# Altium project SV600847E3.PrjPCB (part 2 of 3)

## Sheet SV600847E3_4_LMK04828.SchDoc
size 431 x 279 mm; Date: Not shown in title block; ApprovedBy: Not shown in title block; CheckedBy: Not shown in title block; Author: Not shown in title block; CompanyName: Not shown in title block; Engineer: Not shown in title block; Organization: Not shown in title block; Address1: Not shown in title block; Address2: Not shown in title block; Address3: Not shown in title block; Address4: Not shown in title block; DocumentNumber: 4; Revision: Use project parameter SCH_Rev; SheetNumber: 4; SheetTotal: 7; PageSetup: Record=PageOptions|CenterHorizontal=True|CenterVertical=True|PrintScale=0.47|XCorrection=1.00|YCorrection=1.00|PrintKind=0|BorderSize=5000000|LeftOffset=0|BottomOffset=0|Orientation=2|PaperLength=1000|PaperWidth=1000|Scale=100|PaperSource=7|PrintQuality=600|MediaType=1|DitherType=10|PaperKind=11" x 17"|PrintScaleMode=1
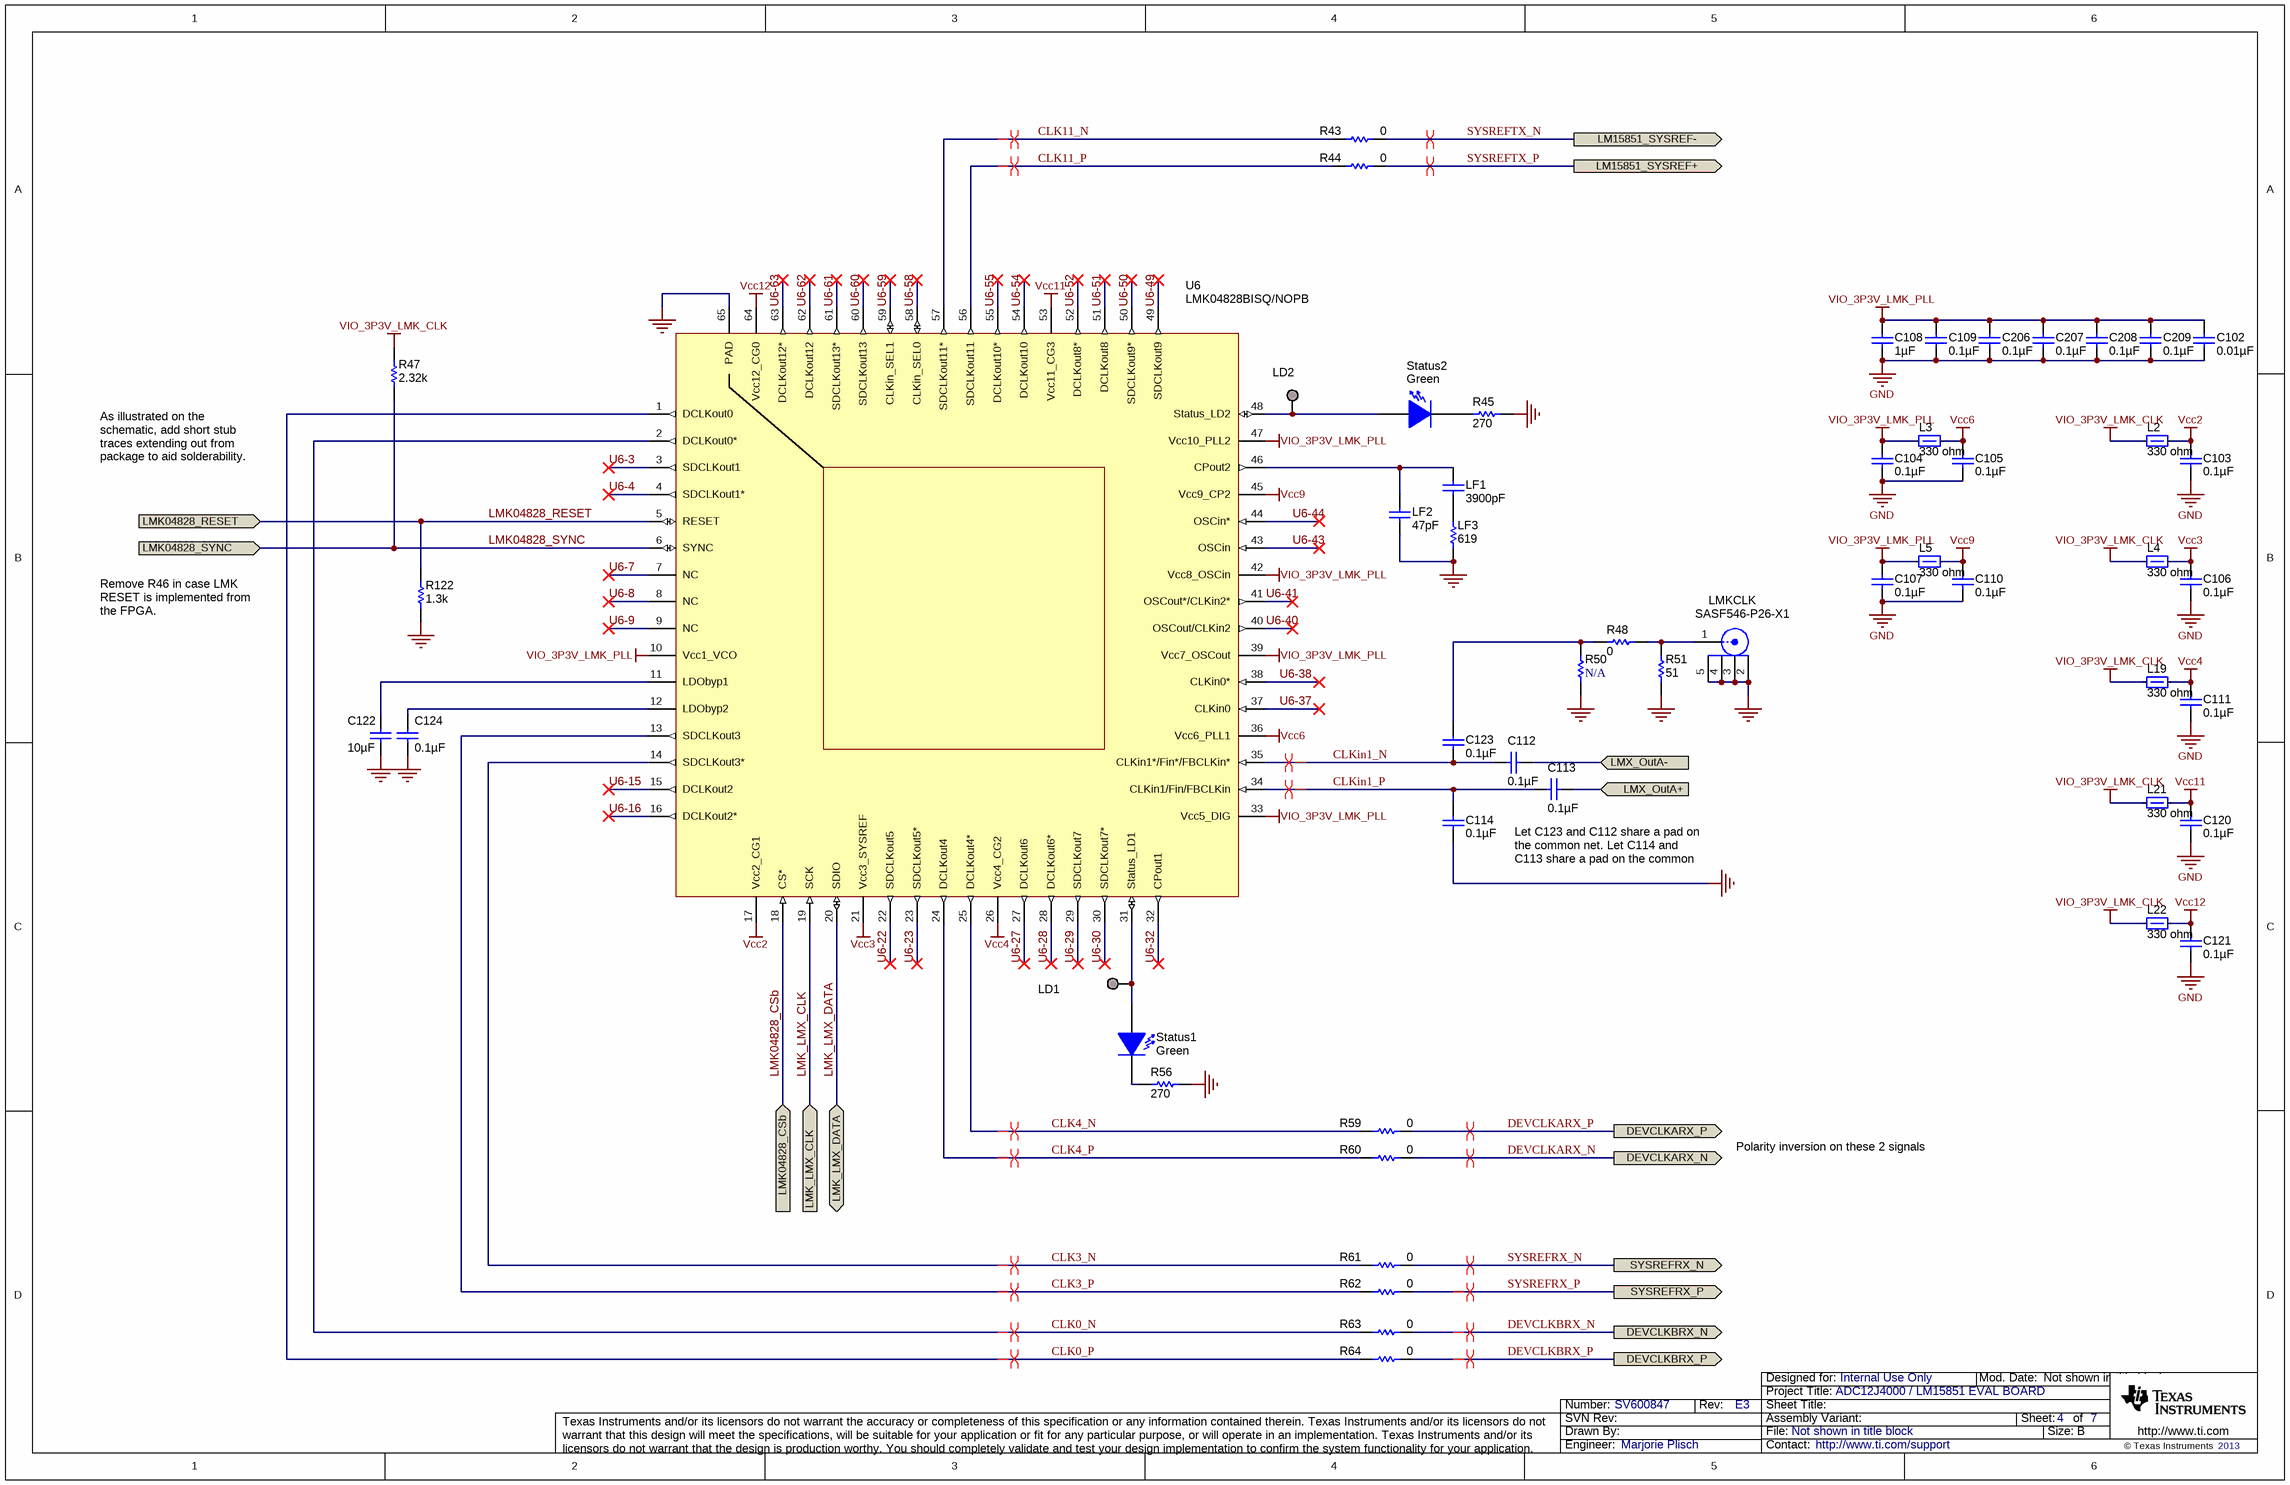
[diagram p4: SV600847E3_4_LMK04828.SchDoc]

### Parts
C102  ValueDisplayed: 0.01µF  [0402L]  (hidden comment: C1005X7R1C103K)
C103  ValueDisplayed: 0.1µF  [0402L]  (hidden comment: C1005X5R1A104K)
C104  ValueDisplayed: 0.1µF  [0402L]  (hidden comment: C1005X5R1A104K)
C105  ValueDisplayed: 0.1µF  [0402L]  (hidden comment: C1005X5R1A104K)
C106  ValueDisplayed: 0.1µF  [0402L]  (hidden comment: C1005X5R1A104K)
C107  ValueDisplayed: 0.1µF  [0402L]  (hidden comment: C1005X5R1A104K)
C108  ValueDisplayed: 1µF  [0603L]  (hidden comment: C1608X5R1C105K)
C109  ValueDisplayed: 0.1µF  [0402L]  (hidden comment: C1005X5R1A104K)
C110  ValueDisplayed: 0.1µF  [0402L]  (hidden comment: C1005X5R1A104K)
C111  ValueDisplayed: 0.1µF  [0402L]  (hidden comment: C1005X5R1A104K)
C112  ValueDisplayed: 0.1µF  [0402L]  (hidden comment: C1005X5R1A104K)
C113  ValueDisplayed: 0.1µF  [0402L]  (hidden comment: C1005X5R1A104K)
C114  ValueDisplayed: 0.1µF  [0402L]  (hidden comment: C1005X5R1A104K)
C120  ValueDisplayed: 0.1µF  [0402L]  (hidden comment: C1005X5R1A104K)
C121  ValueDisplayed: 0.1µF  [0402L]  (hidden comment: C1005X5R1A104K)
C122  ValueDisplayed: 10µF  [0805L]  (hidden comment: C0805C106K8PACTU)
C123  ValueDisplayed: 0.1µF  [0402L]  (hidden comment: C1005X5R1A104K)
C124  ValueDisplayed: 0.1µF  [0402L]  (hidden comment: C1005X5R1A104K)
C206  ValueDisplayed: 0.1µF  [0402L]  (hidden comment: C1005X5R1A104K)
C207  ValueDisplayed: 0.1µF  [0402L]  (hidden comment: C1005X5R1A104K)
C208  ValueDisplayed: 0.1µF  [0402L]  (hidden comment: C1005X5R1A104K)
C209  ValueDisplayed: 0.1µF  [0402L]  (hidden comment: C1005X5R1A104K)
L2  value 330 ohm  [0603]  (hidden comment: BLM18SG331TN1D)
L3  value 330 ohm  [0603]  (hidden comment: BLM18SG331TN1D)
L4  value 330 ohm  [0603]  (hidden comment: BLM18SG331TN1D)
L5  value 330 ohm  [0603]  (hidden comment: BLM18SG331TN1D)
L19  value 330 ohm  [0603]  (hidden comment: BLM18SG331TN1D)
L21  value 330 ohm  [0603]  (hidden comment: BLM18SG331TN1D)
L22  value 330 ohm  [0603]  (hidden comment: BLM18SG331TN1D)
LD1  TESTPOINT  [TESTPOINT]  (value not drawn)  (no BOM)
LD2  TESTPOINT  [TESTPOINT]  (value not drawn)  (no BOM)
LF1  ValueDisplayed: 3900pF  [0603L]  (hidden comment: C1608C0G1E392J)
LF2  ValueDisplayed: 47pF  [0603L]  (hidden comment: 06035A470JAT2A)
LF3  value 619  [0603L]  (hidden comment: RC0603FR-07619RL)
LMKCLK  SASF546-P26-X1  [CONN_LTI_SASF546-P26-X1]
R43  value 0  [0402L]  (hidden comment: CRCW04020000Z0ED)
R44  value 0  [0402L]  (hidden comment: CRCW04020000Z0ED)
R45  value 270  [0603L]  (hidden comment: CRCW0603270RJNEA)
R47  value 2.32k  [0603L]  (hidden comment: RC0603FR-072K32L)
R48  value 0  [0402L]  (hidden comment: CRCW04020000Z0ED)
R50  (no value)  [0402L]
R51  value 51  [0402L]  (hidden comment: CRCW040251R0JNED)
R56  value 270  [0603L]  (hidden comment: CRCW0603270RJNEA)
R59  value 0  [0402L]  (hidden comment: CRCW04020000Z0ED)
R60  value 0  [0402L]  (hidden comment: CRCW04020000Z0ED)
R61  value 0  [0402L]  (hidden comment: CRCW04020000Z0ED)
R62  value 0  [0402L]  (hidden comment: CRCW04020000Z0ED)
R63  value 0  [0402L]  (hidden comment: CRCW04020000Z0ED)
R64  value 0  [0402L]  (hidden comment: CRCW04020000Z0ED)
R122  value 1.3k  [0603L]  (hidden comment: RC0603JR-071K3L)
Status1  value Green  [LED_LTST-C190]  (hidden comment: LTST-C190GKT)
Status2  value Green  [LED_LTST-C190]  (hidden comment: LTST-C190GKT)
U6  LMK04828BISQ/NOPB  [NKD0064A]

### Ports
DEVCLKARX_N (out), DEVCLKARX_P (out), DEVCLKBRX_N (out), DEVCLKBRX_P (out), LM15851_SYSREF+ (out), LM15851_SYSREF- (out), LMK04828_CSb (in), LMK04828_RESET (in), LMK04828_SYNC (in), LMK_LMX_CLK (in), LMK_LMX_DATA (bidir), LMX_OutA+ (in), LMX_OutA- (in), SYSREFRX_N (out), SYSREFRX_P (out)

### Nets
GND: C102.2 C103.2 C104.2 C105.2 C106.2 C107.2 C108.2 C109.2 C110.2 C111.2 C114.1 C120.2 C121.2 C122.2 C124.2 C206.2 C207.2 C208.2 C209.2 LF2.2 LF3.1 LMKCLK.2 LMKCLK.3 LMKCLK.4 LMKCLK.5 R45.1 R50.2 R51.1 R56.1 R122.1 U6.65(PAD)
Vcc2: C103.1 L2.2 U6.17(Vcc2_CG1)
Vcc3: C106.1 L4.2 U6.21(Vcc3_SYSREF)
Vcc4: C111.1 L19.2 U6.26(Vcc4_CG2)
Vcc6: C105.1 L3.2 U6.36(Vcc6_PLL1)
Vcc9: C110.1 L5.2 U6.45(Vcc9_CP2)
Vcc11: C120.1 L21.2 U6.53(Vcc11_CG3)
Vcc12: C121.1 L22.2 U6.64(Vcc12_CG0)
VIO_3P3V_LMK_CLK: L2.1 L4.1 L19.1 L21.1 L22.1 R47.2
VIO_3P3V_LMK_PLL: C102.1 C104.1 C107.1 C108.1 C109.1 C206.1 C207.1 C208.1 C209.1 L3.1 L5.1 U6.10(Vcc1_VCO) U6.33(Vcc5_DIG) U6.39(Vcc7_OSCout) U6.42(Vcc8_OSCin) U6.47(Vcc10_PLL2)
CLK0_N: R63.1 U6.2(DCLKout0*)
CLK0_P: R64.1 U6.1(DCLKout0)
CLK3_N: R61.1 U6.14(SDCLKout3*)
CLK3_P: R62.1 U6.13(SDCLKout3)
CLK4_N: R59.1 U6.25(DCLKout4*)
CLK4_P: R60.1 U6.24(DCLKout4)
CLK11_N: R43.1 U6.57(SDCLKout11*)
CLK11_P: R44.1 U6.56(SDCLKout11)
CLKin1_N: C112.1 C123.1 U6.35(CLKin1*/Fin*/FBCLKin*)
CLKin1_P: C113.1 C114.2 U6.34(CLKin1/Fin/FBCLKin)
DEVCLKARX_N: R60.2 ; port DEVCLKARX_N
DEVCLKARX_P: R59.2 ; port DEVCLKARX_P
DEVCLKBRX_N: R63.2 ; port DEVCLKBRX_N
DEVCLKBRX_P: R64.2 ; port DEVCLKBRX_P
LMK04828_CSb: U6.18(CS*) ; port LMK04828_CSb
LMK04828_RESET: R122.2 U6.5(RESET) ; port LMK04828_RESET
LMK04828_SYNC: R47.1 U6.6(SYNC) ; port LMK04828_SYNC
LMK_LMX_CLK: U6.19(SCK) ; port LMK_LMX_CLK
LMK_LMX_DATA: U6.20(SDIO) ; port LMK_LMX_DATA
LMX_OutA_N: C112.2 ; port LMX_OutA-
LMX_OutA_P: C113.2 ; port LMX_OutA+
SYSREFRX_N: R61.2 ; port SYSREFRX_N
SYSREFRX_P: R62.2 ; port SYSREFRX_P
SYSREFTX_N: R43.2 ; port LM15851_SYSREF-
SYSREFTX_P: R44.2 ; port LM15851_SYSREF+
U6-3: U6.3(SDCLKout1)
U6-4: U6.4(SDCLKout1*)
U6-7: U6.7(NC)
U6-8: U6.8(NC)
U6-9: U6.9(NC)
U6-15: U6.15(DCLKout2)
U6-16: U6.16(DCLKout2*)
U6-22: U6.22(SDCLKout5)
U6-23: U6.23(SDCLKout5*)
U6-27: U6.27(DCLKout6)
U6-28: U6.28(DCLKout6*)
U6-29: U6.29(SDCLKout7)
U6-30: U6.30(SDCLKout7*)
U6-32: U6.32(CPout1)
U6-37: U6.37(CLKin0)
U6-38: U6.38(CLKin0*)
U6-40: U6.40(OSCout/CLKin2)
U6-41: U6.41(OSCout*/CLKin2*)
U6-43: U6.43(OSCin)
U6-44: U6.44(OSCin*)
U6-49: U6.49(SDCLKout9)
U6-50: U6.50(SDCLKout9*)
U6-51: U6.51(DCLKout8)
U6-52: U6.52(DCLKout8*)
U6-54: U6.54(DCLKout10)
U6-55: U6.55(DCLKout10*)
U6-58: U6.58(CLKin_SEL0)
U6-59: U6.59(CLKin_SEL1)
U6-60: U6.60(SDCLKout13)
U6-61: U6.61(SDCLKout13*)
U6-62: U6.62(DCLKout12)
U6-63: U6.63(DCLKout12*)
NetC122_1: C122.1 U6.11(LDObyp1)
NetC123_2: C123.2 R48.1 R50.1
NetC124_1: C124.1 U6.12(LDObyp2)
NetLD1_1: LD1.1 Status1.1(A) U6.31(Status_LD1)
NetLD2_1: LD2.1 Status2.1(A) U6.48(Status_LD2)
NetLF1_1: LF1.1 LF2.1 U6.46(CPout2)
NetLF1_2: LF1.2 LF3.2
NetLMKCLK_1: LMKCLK.1 R48.2 R51.2
NetR45_2: R45.2 Status2.2(K)
NetR56_2: R56.2 Status1.2(K)

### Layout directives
differential pair: CLK0_N, CLK0_P, CLK3_N, CLK3_P, CLK4_N, CLK4_P, CLK11_N, CLK11_P, CLKin1_N, CLKin1_P, DEVCLKARX_N, DEVCLKARX_P, DEVCLKBRX_N, DEVCLKBRX_P, SYSREFRX_N, SYSREFRX_P, SYSREFTX_N, SYSREFTX_P

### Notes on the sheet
- As illustrated on the schematic, add short stub traces extending out from package to aid solderability.
- Remove R46 in case LMK RESET is implemented from the FPGA.
- (near C113) Let C123 and C112 share a pad on the common net. Let C114 and C113 share a pad on the common net.
- Polarity inversion on these 2 signals

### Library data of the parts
C102 = C1005X7R1C103K: CAP, CERM, 0.01uF, 16V, +/-10%, X7R, 0402; Manufacturer: TDK; Polarized: N; CompType: Capacitor; U/M: EA; Cap_F: 0.00000001; Tolerance_%: 10; ESR_Ohm: 0.0623; Value1: 0.0623 ohm; VDC_V: 16; TaMin_C: -55; TaMax_C: 125; Cap_Case: 0402
C103-C107 C109-C114 C120 C121 C123 C124 C206-C209 = C1005X5R1A104K: CAP, CERM, 0.1uF, 10V, +/-10%, X5R, 0402; Manufacturer: TDK; Polarized: N; CompType: Capacitor; U/M: EA; Cap_F: 0.0000001; Tolerance_%: 10; ESR_Ohm: 0.0186; Value1: 0.0186 ohm; TaMin_C: -55; TaMax_C: 85; Cap_Case: 0402
C108 = C1608X5R1C105K: CAP, CERM, 1uF, 16V, +/-10%, X5R, 0603; Manufacturer: TDK; Polarized: N; CompType: Capacitor; U/M: EA; Cap_F: 0.000001; Tolerance_%: 10; ESR_Ohm: 0.0057; Value1: 0.0057 ohm; VDC_V: 16; TaMin_C: -55; TaMax_C: 85; Cap_Case: 0603
C122 = C0805C106K8PACTU: CAP, CERM, 10uF, 10V, +/-10%, X5R, 0805; Manufacturer: Kemet; Cap_Case: 0805; ESR_Ohm: 0.003; IRMS_A: 11.43; Polarized: N; TaMax_C: 85; TaMin_C: -55; Tolerance_%: 10; Cap_F: 10.0E-6; CompType: Capacitor; Value1: 0.003 ohm
L2-L5 L19 L21 L22 = BLM18SG331TN1D: 1.5A Ferrite Bead, 330 ohm @ 100MHz, SMD; Manufacturer: MuRata; Imax_A: 1.5; DCR_ohm: 0.07; Value1: 0.07 ohm; ZTyp@100MHz_Ohm: 330; U/M: EA
LD1 LD2 = TESTPOINT: TEST POINT.  No entry in BOM.
LF1 = C1608C0G1E392J: CAP, CERM, 3900pF, 25V, +/-5%, C0G/NP0, 0603; Manufacturer: TDK; Polarized: N; CompType: Capacitor; U/M: EA; Cap_F: 0.0000000039; Tolerance_%: 5; VDC_V: 25; TaMin_C: -55; TaMax_C: 125; Cap_Case: 0603
LF2 = 06035A470JAT2A: CAP, CERM, 47pF, 50V, +/-5%, C0G/NP0, 0603; Manufacturer: AVX; Polarized: N; CompType: Capacitor; U/M: EA; Cap_F: 0.000000000047; Tolerance_%: 5; ESR_Ohm: 0.174; Value1: 0.174 ohm; VDC_V: 50; TaMin_C: -55; TaMax_C: 125; Cap_Case: 0603
LF3 = RC0603FR-07619RL: RES, 619 ohm, 1%, 0.1W, 0603; Manufacturer: Yageo America; Alternate Manufacturer: Any; Alternate PartNumber: Equivalent; CompType: Resistor; Value_Code: 619R; Tolerance_%: 1; Power_W: 0.1; VDC_V: 150; TempCo: 200 ppm/C; EIA_Code: E96; U/M: EA
LMKCLK = SASF546-P26-X1: Connector, SMA,Vertical, Thru hole w/SMT center pin; Manufacturer: Lighthorse Technologies; U/M: EA
R43 R44 R59-R64 = CRCW04020000Z0ED: RES, 0 ohm, 5%, 0.063W, 0402; Manufacturer: Vishay-Dale; CompType: Resistor; Value_Code: 0000; Tolerance_%: 5; Power_W: 0.063; VDC_V: 50; TempCo: 200 ppm/C; EIA_Code: E24; U/M: EA
R45 R56 = CRCW0603270RJNEA: RES, 270 ohm, 5%, 0.1W, 0603; Manufacturer: Vishay-Dale; Alternate Manufacturer: Any; Alternate PartNumber: Equivalent; CompType: Resistor; Value_Code: 270R; Tolerance_%: 5; Power_W: 0.1; VDC_V: 75; TempCo: 200 ppm/C; EIA_Code: E24; U/M: EA
R47 = RC0603FR-072K32L: RES, 2.32k ohm, 1%, 0.1W, 0603; Manufacturer: Yageo America; CompType: Resistor; Res_ohm: 2320; Value_Code: 2k32; Tolerance_%: 1; Power_W: 0.1; VDC_V: 150; TempCo: 200 ppm/C; EIA_Code: E96; U/M: EA
R48 = CRCW04020000Z0ED: RES, 0 ohm, 5%, 0.063W, 0402; Manufacturer: Vishay-Dale; Alternate Manufacturer: Any; Alternate PartNumber: Equivalent; CompType: Resistor; Value_Code: 0000; Tolerance_%: 5; Power_W: 0.063; VDC_V: 50; TempCo: 200 ppm/C; EIA_Code: E24; U/M: EA
R50 = Res 0402 placeholder_1: Generic symbol for 0402 Res placeholder; CompType: Resistor
R51 = CRCW040251R0JNED: RES, 51 ohm, 5%, 0.063W, 0402; Manufacturer: Vishay-Dale; Alternate Manufacturer: Any; Alternate PartNumber: Equivalent; CompType: Resistor; Value_Code: 51R0; Tolerance_%: 5; Power_W: 0.063; VDC_V: 50; TempCo: 200 ppm/C; EIA_Code: E24; U/M: EA
R122 = RC0603JR-071K3L: RES, 1.3k ohm, 5%, 0.1W, 0603; Manufacturer: Yageo America; CompType: Resistor; Res_ohm: 1300; Value_Code: 1k30; Tolerance_%: 5; Power_W: 0.1; VDC_V: 50; TempCo: 100 ppm/C; EIA_Code: E24; U/M: EA
Status1 Status2 = LTST-C190GKT: LED, Green, SMD; Manufacturer: Lite-On; Vf_V: 2.1; Value2: 2.1V; Io_A: 0.02; Power_TotalModule: 0.1; Value1: 0.1W; U/M: EA
U6 = LMK04828BISQ/NOPB: Low-Noise Clock Jitter Cleaner with Dual Loop PLLs, NKD0064A; Alternate Manufacturer: None; Manufacturer: Texas Instruments; SymbolCreator: a0411947/a0412235; CompType: IC; U/M: EA

## Sheet SV600847E3_5_Power.SchDoc
size 431 x 279 mm; Date: Not shown in title block; ApprovedBy: Not shown in title block; CheckedBy: Not shown in title block; Author: Not shown in title block; CompanyName: Not shown in title block; Engineer: Not shown in title block; Organization: Not shown in title block; Address1: Not shown in title block; Address2: Not shown in title block; Address3: Not shown in title block; Address4: Not shown in title block; DocumentNumber: 5; Revision: Use project parameter SCH_Rev; SheetNumber: 5; SheetTotal: 7; PageSetup: Record=PageOptions|CenterHorizontal=True|CenterVertical=True|PrintScale=0.64|XCorrection=1.00|YCorrection=1.00|PrintKind=0|BorderSize=5000000|LeftOffset=0|BottomOffset=0|Orientation=2|PaperLength=1000|PaperWidth=1000|Scale=100|PaperSource=15|PrintQuality=600|MediaType=1|DitherType=10|PaperKind=11x17|PrintScaleMode=1
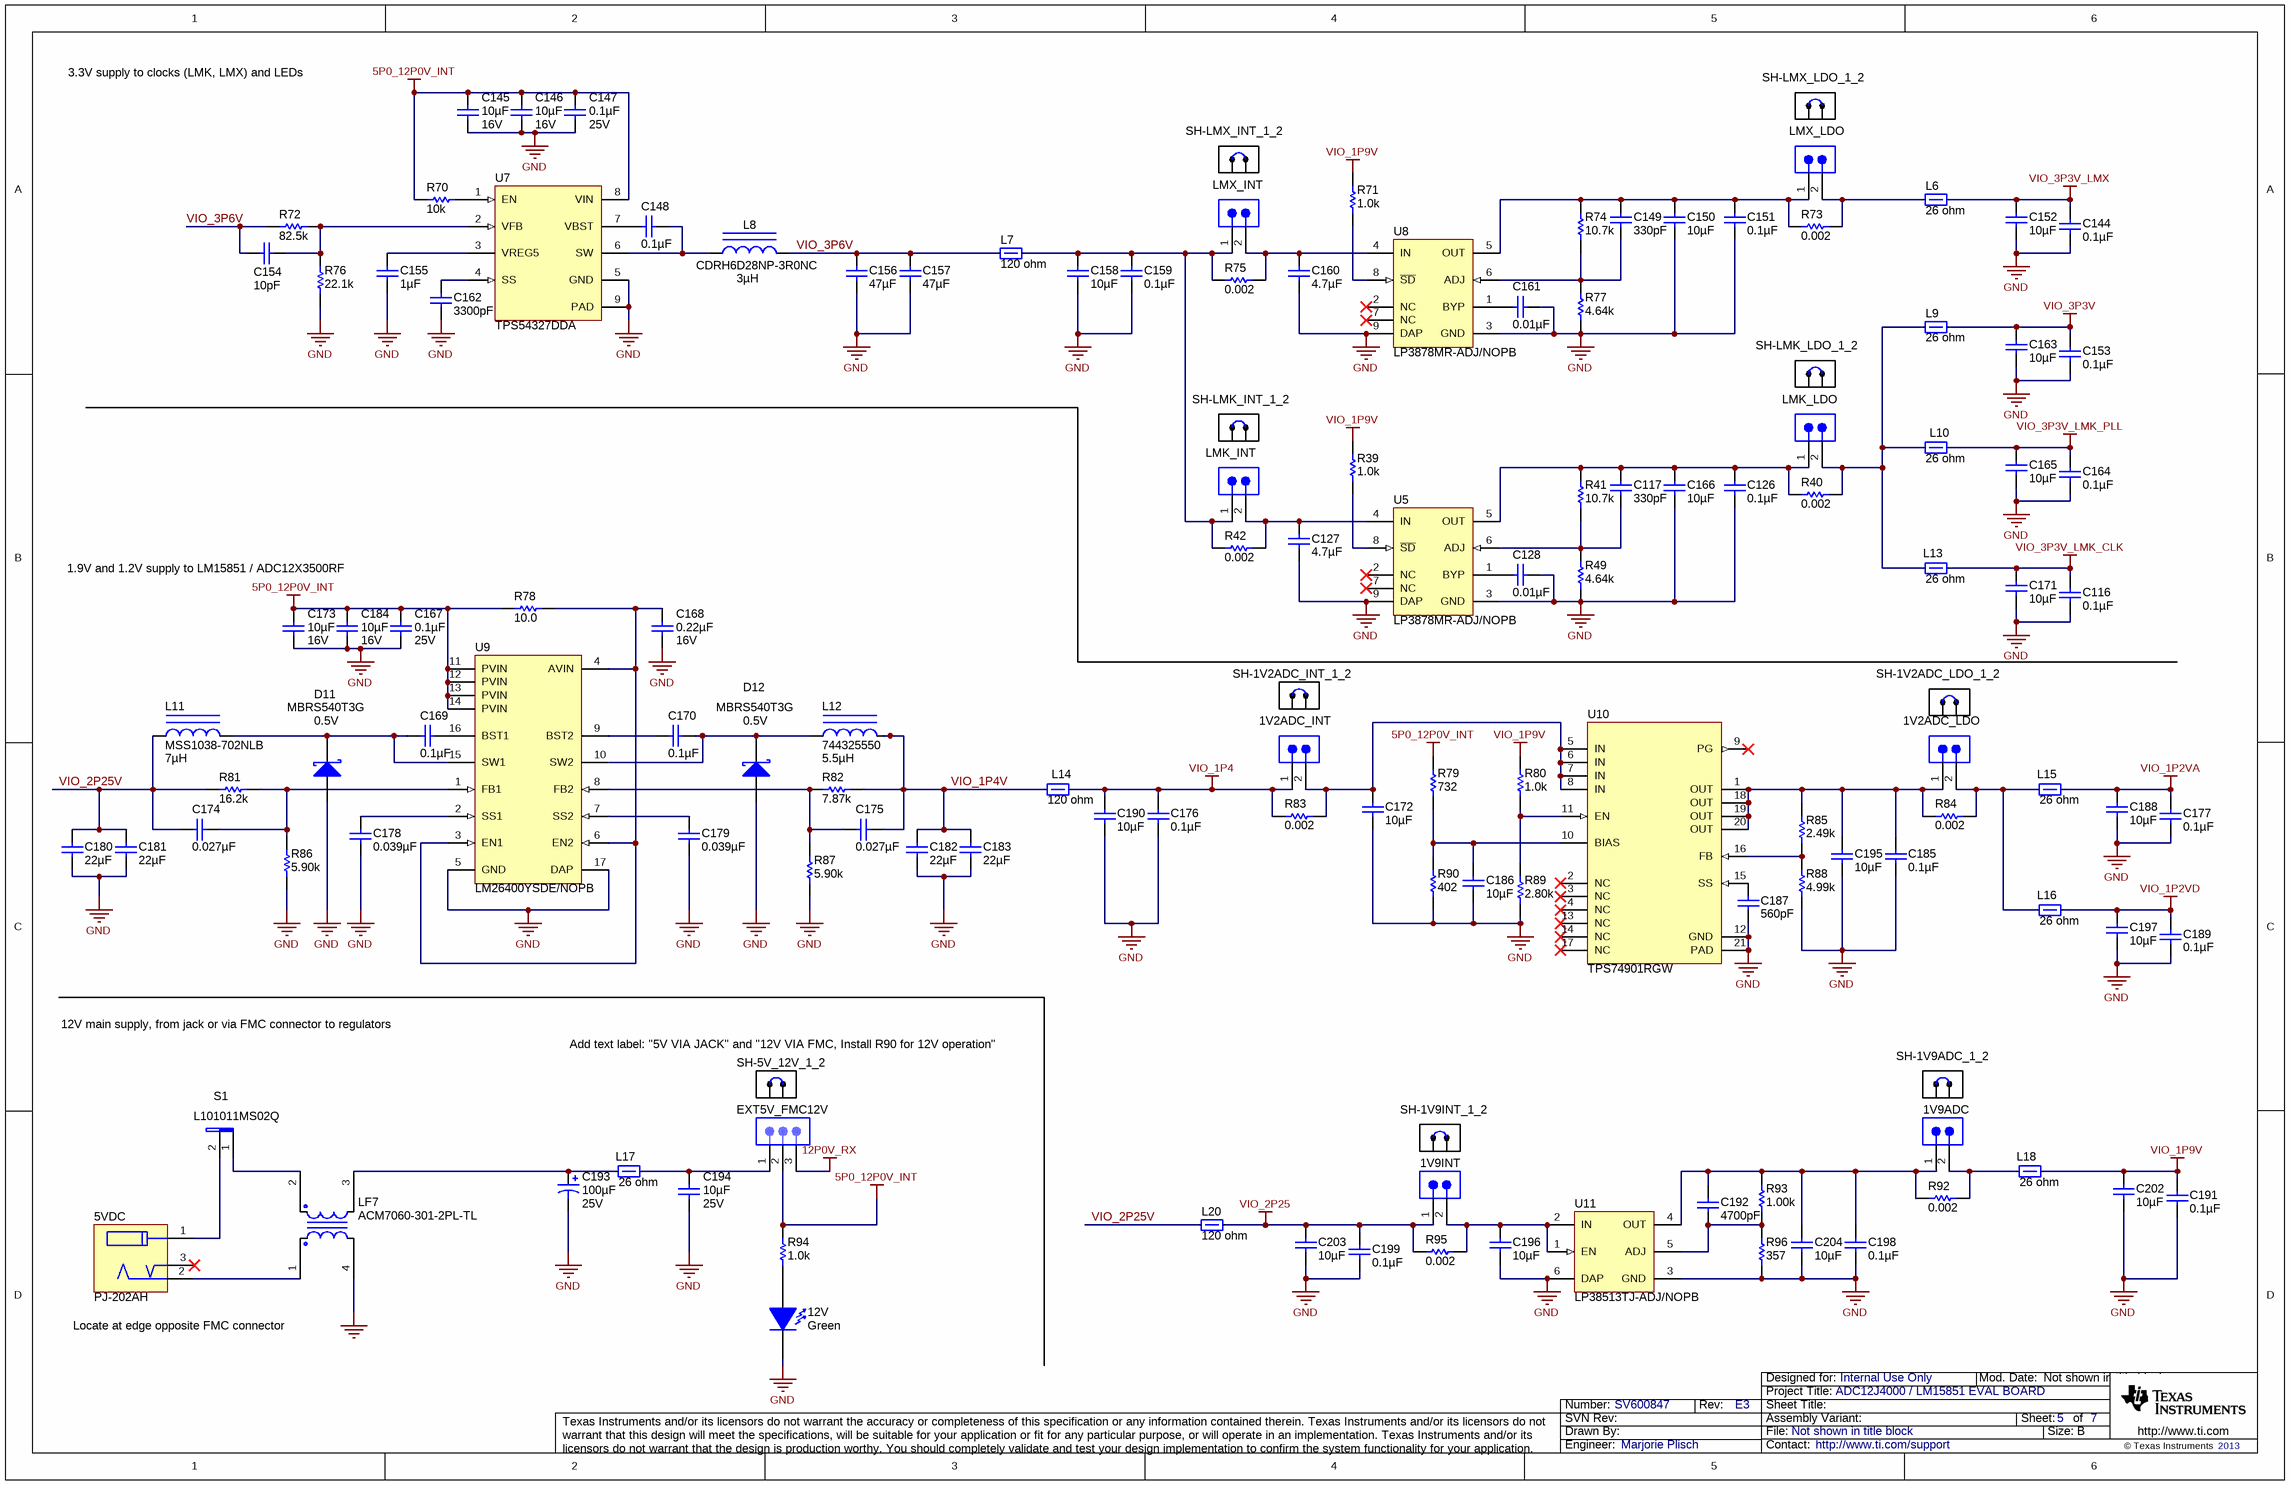
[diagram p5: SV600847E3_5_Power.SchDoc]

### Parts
1V2ADC_INT  TSW-102-07-G-S  [TSW-102-07-G-S]  (value not drawn)
1V2ADC_LDO  TSW-102-07-G-S  [TSW-102-07-G-S]  (value not drawn)
1V9ADC  TSW-102-07-G-S  [TSW-102-07-G-S]  (value not drawn)
1V9INT  TSW-102-07-G-S  [TSW-102-07-G-S]  (value not drawn)
5VDC  PJ-202AH  [CONN_CUI-PJ-202AH]
12V  value Green  [LED_LTST-C190]  (hidden comment: LTST-C190GKT)
C116  ValueDisplayed: 0.1µF  [0603L]  (hidden comment: 06033C104JAT2A)
C117  ValueDisplayed: 330pF  [0603L]  (hidden comment: 06035A331JAT2A)
C126  ValueDisplayed: 0.1µF  [0603L]  (hidden comment: 06033C104JAT2A)
C127  ValueDisplayed: 4.7µF  [0603L]  (hidden comment: C0603C475K8PACTU)
C128  ValueDisplayed: 0.01µF  [0603L]  (hidden comment: 06031C103MAT2A)
C144  ValueDisplayed: 0.1µF  [0603L]  (hidden comment: 06033C104JAT2A)
C145  ValueDisplayed: 10µF  Value2: 16V  [0805L]  (hidden comment: EMK212BJ106KG-T)
C146  ValueDisplayed: 10µF  Value2: 16V  [0805L]  (hidden comment: EMK212BJ106KG-T)
C147  ValueDisplayed: 0.1µF  Value2: 25V  [0603L]  (hidden comment: 06033C104JAT2A)
C148  ValueDisplayed: 0.1µF  [0603L]  (hidden comment: 06033C104JAT2A)
C149  ValueDisplayed: 330pF  [0603L]  (hidden comment: 06035A331JAT2A)
C150  ValueDisplayed: 10µF  [0603L]  (hidden comment: C1608X5R1A106M)
C151  ValueDisplayed: 0.1µF  [0603L]  (hidden comment: 06033C104JAT2A)
C152  ValueDisplayed: 10µF  [0603L]  (hidden comment: C1608X5R1A106M)
C153  ValueDisplayed: 0.1µF  [0603L]  (hidden comment: 06033C104JAT2A)
C154  ValueDisplayed: 10pF  [0603L]  (hidden comment: 06035A100JAT2A)
C155  ValueDisplayed: 1µF  [0603L]  (hidden comment: C1608X5R1C105K)
C156  ValueDisplayed: 47µF  [1206L]  (hidden comment: GRM31CR60J476ME19L)
C157  ValueDisplayed: 47µF  [1206L]  (hidden comment: GRM31CR60J476ME19L)
C158  ValueDisplayed: 10µF  [0603L]  (hidden comment: C1608X5R1A106M)
C159  ValueDisplayed: 0.1µF  [0603L]  (hidden comment: 06033C104JAT2A)
C160  ValueDisplayed: 4.7µF  [0603L]  (hidden comment: C0603C475K8PACTU)
C161  ValueDisplayed: 0.01µF  [0603L]  (hidden comment: 06031C103MAT2A)
C162  ValueDisplayed: 3300pF  [0603L]  (hidden comment: GRM188R71E332KA01D)
C163  ValueDisplayed: 10µF  [0603L]  (hidden comment: C1608X5R1A106M)
C164  ValueDisplayed: 0.1µF  [0603L]  (hidden comment: 06033C104JAT2A)
C165  ValueDisplayed: 10µF  [0603L]  (hidden comment: C1608X5R1A106M)
C166  ValueDisplayed: 10µF  [0603L]  (hidden comment: C1608X5R1A106M)
C167  ValueDisplayed: 0.1µF  Value2: 25V  [0603L]  (hidden comment: 06033C104JAT2A)
C168  ValueDisplayed: 0.22µF  Value2: 16V  [0603L]  (hidden comment: C1608X7R1C224K)
C169  ValueDisplayed: 0.1µF  [0402L]  (hidden comment: GRM155R60J104KA01D)
C170  ValueDisplayed: 0.1µF  [0402L]  (hidden comment: GRM155R60J104KA01D)
C171  ValueDisplayed: 10µF  [0603L]  (hidden comment: C1608X5R1A106M)
C172  ValueDisplayed: 10µF  [0603L]  (hidden comment: C1608X5R1A106M)
C173  ValueDisplayed: 10µF  Value2: 16V  [0805L]  (hidden comment: EMK212BJ106KG-T)
C174  ValueDisplayed: 0.027µF  [0603L]  (hidden comment: GRM188R71C273KA01D)
C175  ValueDisplayed: 0.027µF  [0603L]  (hidden comment: GRM188R71C273KA01D)
C176  ValueDisplayed: 0.1µF  [0603L]  (hidden comment: 06033C104JAT2A)
C177  ValueDisplayed: 0.1µF  [0603L]  (hidden comment: 06033C104JAT2A)
C178  ValueDisplayed: 0.039µF  [0603L]  (hidden comment: 06033C393KAT2A)
C179  ValueDisplayed: 0.039µF  [0603L]  (hidden comment: 06033C393KAT2A)
C180  ValueDisplayed: 22µF  [1206L]  (hidden comment: GRM31CR61A226ME19L)
C181  ValueDisplayed: 22µF  [1206L]  (hidden comment: GRM31CR61A226ME19L)
C182  ValueDisplayed: 22µF  [1206L]  (hidden comment: GRM31CR61A226ME19L)
C183  ValueDisplayed: 22µF  [1206L]  (hidden comment: GRM31CR61A226ME19L)
C184  ValueDisplayed: 10µF  Value2: 16V  [0805L]  (hidden comment: EMK212BJ106KG-T)
C185  ValueDisplayed: 0.1µF  [0603L]  (hidden comment: 06033C104JAT2A)
C186  ValueDisplayed: 10µF  [0603L]  (hidden comment: C1608X5R1A106M)
C187  ValueDisplayed: 560pF  [0603L]  (hidden comment: 06035A561JAT2A)
C188  ValueDisplayed: 10µF  [0603L]  (hidden comment: C1608X5R1A106M)
C189  ValueDisplayed: 0.1µF  [0603L]  (hidden comment: 06033C104JAT2A)
C190  ValueDisplayed: 10µF  [0603L]  (hidden comment: C1608X5R1A106M)
C191  ValueDisplayed: 0.1µF  [0603L]  (hidden comment: 06033C104JAT2A)
C192  ValueDisplayed: 4700pF  [0603L]  (hidden comment: GRM188R71C472KA01D)
C193  ValueDisplayed: 100µF  Value2: 25V  [SM_RADIAL_F]  (hidden comment: EEE-FC1E101P)
C194  ValueDisplayed: 10µF  Value2: 25V  [1210L]  (hidden comment: GRM32DC81E106KA12L)
C195  ValueDisplayed: 10µF  [0603L]  (hidden comment: C1608X5R1A106M)
C196  ValueDisplayed: 10µF  [0603L]  (hidden comment: C1608X5R1A106M)
C197  ValueDisplayed: 10µF  [0603L]  (hidden comment: C1608X5R1A106M)
C198  ValueDisplayed: 0.1µF  [0603L]  (hidden comment: 06033C104JAT2A)
C199  ValueDisplayed: 0.1µF  [0603L]  (hidden comment: 06033C104JAT2A)
C202  ValueDisplayed: 10µF  [0603L]  (hidden comment: C1608X5R1A106M)
C203  ValueDisplayed: 10µF  [0603L]  (hidden comment: C1608X5R1A106M)
C204  ValueDisplayed: 10µF  [0603L]  (hidden comment: C1608X5R1A106M)
D11  MBRS540T3G  value 0.5V  [SMC]
D12  MBRS540T3G  value 0.5V  [SMC]
EXT5V_FMC12V  PBC03SAAN  [PBC03SAAN]  (value not drawn)
L6  value 26 ohm  [0603]  (hidden comment: BLM18SG260TN1D)
L7  value 120 ohm  [0603]  (hidden comment: BLM18SG121TN1D)
L8  CDRH6D28NP-3R0NC  ValueDisplayed: 3µH  [CDRH6D28]
L9  value 26 ohm  [0603]  (hidden comment: BLM18SG260TN1D)
L10  value 26 ohm  [0603]  (hidden comment: BLM18SG260TN1D)
L11  MSS1038-702NLB  ValueDisplayed: 7µH  [MSS1038]
L12  744325550  ValueDisplayed: 5.5µH  [WE-HC6]
L13  value 26 ohm  [0603]  (hidden comment: BLM18SG260TN1D)
L14  value 120 ohm  [0603]  (hidden comment: BLM18SG121TN1D)
L15  value 26 ohm  [0603]  (hidden comment: BLM18SG260TN1D)
L16  value 26 ohm  [0603]  (hidden comment: BLM18SG260TN1D)
L17  value 26 ohm  [0603]  (hidden comment: BLM18SG260TN1D)
L18  value 26 ohm  [0603]  (hidden comment: BLM18SG260TN1D)
L20  value 120 ohm  [0603]  (hidden comment: BLM18SG121TN1D)
LF7  ACM7060-301-2PL-TL  [IND_TDK_ACM7060]
LMK_INT  TSW-102-07-G-S  [TSW-102-07-G-S]  (value not drawn)
LMK_LDO  TSW-102-07-G-S  [TSW-102-07-G-S]  (value not drawn)
LMX_INT  TSW-102-07-G-S  [TSW-102-07-G-S]  (value not drawn)
LMX_LDO  TSW-102-07-G-S  [TSW-102-07-G-S]  (value not drawn)
R39  value 1.0k  [0603L]  (hidden comment: RC0603JR-071KL)
R40  value 0.002  [1206]  (hidden comment: CSNL1206FT2L00)
R41  value 10.7k  [0603L]  (hidden comment: CRCW060310K7FKEA)
R42  value 0.002  [1206]  (hidden comment: CSNL1206FT2L00)
R49  value 4.64k  [0603L]  (hidden comment: RC0603FR-074K64L)
R70  value 10k  [0603L]  (hidden comment: RC0603JR-0710KL)
R71  value 1.0k  [0603L]  (hidden comment: RC0603JR-071KL)
R72  value 82.5k  [0603L]  (hidden comment: CRCW060382K5FKEA)
R73  value 0.002  [1206]  (hidden comment: CSNL1206FT2L00)
R74  value 10.7k  [0603L]  (hidden comment: CRCW060310K7FKEA)
R75  value 0.002  [1206]  (hidden comment: CSNL1206FT2L00)
R76  value 22.1k  [0603L]  (hidden comment: CRCW060322K1FKEA)
R77  value 4.64k  [0603L]  (hidden comment: RC0603FR-074K64L)
R78  value 10.0  [0603L]  (hidden comment: RC0603FR-0710RL)
R79  value 732  [0603L]  (hidden comment: CRCW0603732RFKEA)
R80  value 1.0k  [0603L]  (hidden comment: RC0603JR-071KL)
R81  value 16.2k  [0603L]  (hidden comment: CRCW060316K2FKEA)
R82  value 7.87k  [0603L]  (hidden comment: CRCW06037K87FKEA)
R83  value 0.002  [1206]  (hidden comment: CSNL1206FT2L00)
R84  value 0.002  [1206]  (hidden comment: CSNL1206FT2L00)
R85  value 2.49k  [0603L]  (hidden comment: CRCW06032K49FKEA)
R86  value 5.90k  [0603L]  (hidden comment: CRCW06035K90FKEA)
R87  value 5.90k  [0603L]  (hidden comment: CRCW06035K90FKEA)
R88  value 4.99k  [0603L]  (hidden comment: CRCW06034K99FKEA)
R89  value 2.80k  [0603L]  (hidden comment: CRCW06032K80FKEA)
R90  value 402  [0603L]  (hidden comment: RC0603FR-07402RL)
R92  value 0.002  [1206]  (hidden comment: CSNL1206FT2L00)
R93  value 1.00k  [0603L]  (hidden comment: RC0603FR-071KL)
R94  value 1.0k  [1206L]  (hidden comment: CRCW12061K00JNEA)
R95  value 0.002  [1206]  (hidden comment: CSNL1206FT2L00)
R96  value 357  [0603L]  (hidden comment: RC0603FR-07357RL)
S1  L101011MS02Q  [SW_ L101011MS02Q]
SH-1V2ADC_INT_1_2  SNT-100-BK-G  [SNT-100-BK-G]  (value not drawn)
SH-1V2ADC_LDO_1_2  SNT-100-BK-G  [SNT-100-BK-G]  (value not drawn)
SH-1V9ADC_1_2  SNT-100-BK-G  [SNT-100-BK-G]  (value not drawn)
SH-1V9INT_1_2  SNT-100-BK-G  [SNT-100-BK-G]  (value not drawn)
SH-5V_12V_1_2  SNT-100-BK-G  [SNT-100-BK-G]  (value not drawn)
SH-LMK_INT_1_2  SNT-100-BK-G  [SNT-100-BK-G]  (value not drawn)
SH-LMK_LDO_1_2  SNT-100-BK-G  [SNT-100-BK-G]  (value not drawn)
SH-LMX_INT_1_2  SNT-100-BK-G  [SNT-100-BK-G]  (value not drawn)
SH-LMX_LDO_1_2  SNT-100-BK-G  [SNT-100-BK-G]  (value not drawn)
U5  LP3878MR-ADJ/NOPB  [MRA08A_N]
U7  TPS54327DDA  [DDA0008B_L]
U8  LP3878MR-ADJ/NOPB  [MRA08A_N]
U9  LM26400YSDE/NOPB  [SDA16A]
U10  TPS74901RGW  [RGW0020A]
U11  LP38513TJ-ADJ/NOPB  [TJ5A_N]

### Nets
5P0_12P0V_INT: C145.1 C146.1 C147.1 C167.1 C173.1 C184.1 EXT5V_FMC12V.2 R70.1 R78.1 R79.2 R94.2 U7.8(VIN) U9.11(PVIN) U9.12(PVIN) U9.13(PVIN) U9.14(PVIN)
12P0V_RX: EXT5V_FMC12V.3
GND: 12V.2(K) C116.2 C126.2 C127.2 C128.2 C144.2 C145.2 C146.2 C147.2 C150.2 C151.2 C152.2 C153.2 C155.2 C156.1 C157.1 C158.2 C159.2 C160.2 C161.2 C162.2 C163.2 C164.2 C165.2 C166.2 C167.2 C168.2 C171.2 C172.2 C173.2 C176.2 C177.2 C178.2 C179.2 C180.2 C181.2 C182.2 C183.2 C184.2 C185.2 C186.2 C187.2 C188.2 C189.2 C190.2 C191.2 C193.2(-) C194.2 C195.2 C196.2 C197.2 C198.2 C199.2 C202.2 C203.2 C204.2 D11.2(A) D12.2(A) LF7.4 R49.1 R76.1 R77.1 R86.1 R87.1 R88.1 R89.1 R90.1 R96.1 U5.3(GND) U5.9(DAP) U7.5(GND) U7.9(PAD) U8.3(GND) U8.9(DAP) U9.5(GND) U9.17(DAP) U10.12(GND) U10.21(PAD) U11.3(GND) U11.6(DAP)
VIO_1P2VA: C177.1 C188.1 L15.2
VIO_1P2VD: C189.1 C197.1 L16.2
VIO_1P4: 1V2ADC_INT.1 C176.1 C190.1 L14.2 R83.1
VIO_1P9V: C191.1 C202.1 L18.2 R39.1 R71.1 R80.1
VIO_2P25: 1V9INT.1 C199.1 C203.1 L20.2 R95.1
VIO_3P3V: C153.1 C163.1 L9.2
VIO_3P3V_LMK_CLK: C116.1 C171.1 L13.2
VIO_3P3V_LMK_PLL: C164.1 C165.1 L10.2
VIO_3P3V_LMX: C144.1 C152.1 L6.2
VIO_1P4V: C175.1 C182.1 C183.1 L12.2 L14.1 R82.2
VIO_2P25V: C174.2 C180.1 C181.1 L11.1 L20.1 R81.1
VIO_3P6V: C154.2 C156.2 C157.2 L7.1 L8.2 R72.1
Net1V2ADC_INT_2: 1V2ADC_INT.2 C172.1 R83.2 U10.5(IN) U10.6(IN) U10.7(IN) U10.8(IN)
Net1V2ADC_LDO_1: 1V2ADC_LDO.1 C185.1 C195.1 R84.1 R85.2 U10.1(OUT) U10.18(OUT) U10.19(OUT) U10.20(OUT)
Net1V2ADC_LDO_2: 1V2ADC_LDO.2 L15.1 L16.1 R84.2
Net1V9ADC_1: 1V9ADC.1 C192.1 C198.1 C204.1 R92.1 R93.2 U11.4(OUT)
Net1V9ADC_2: 1V9ADC.2 L18.1 R92.2
Net1V9INT_2: 1V9INT.2 C196.1 R95.2 U11.1(EN) U11.2(IN)
Net5VDC_1: 5VDC.1 S1.2
Net5VDC_2: 5VDC.2 LF7.1
Net12V_1: 12V.1(A) R94.1
NetC117_1: C117.1 C126.1 C166.1 LMK_LDO.1 R40.1 R41.2 U5.5(OUT)
NetC117_2: C117.2 R41.1 R49.2 U5.6(ADJ)
NetC127_1: C127.1 LMK_INT.2 R42.2 U5.4(IN)
NetC128_1: C128.1 U5.1(BYP)
NetC148_1: C148.1 L8.1 U7.6(SW)
NetC148_2: C148.2 U7.7(VBST)
NetC149_1: C149.1 C150.1 C151.1 LMX_LDO.1 R73.1 R74.2 U8.5(OUT)
NetC149_2: C149.2 R74.1 R77.2 U8.6(ADJ)
NetC154_1: C154.1 R72.2 R76.2 U7.2(VFB)
NetC155_1: C155.1 U7.3(VREG5)
NetC158_1: C158.1 C159.1 L7.2 LMK_INT.1 LMX_INT.1 R42.1 R75.1
NetC160_1: C160.1 LMX_INT.2 R75.2 U8.4(IN)
NetC161_1: C161.1 U8.1(BYP)
NetC162_1: C162.1 U7.4(SS)
NetC168_1: C168.1 R78.2 U9.3(EN1) U9.4(AVIN) U9.6(EN2)
NetC169_1: C169.1 U9.16(BST1)
NetC169_2: C169.2 D11.1(K) L11.2 U9.15(SW1)
NetC170_1: C170.1 D12.1(K) L12.1 U9.10(SW2)
NetC170_2: C170.2 U9.9(BST2)
NetC174_1: C174.1 R81.2 R86.2 U9.1(FB1)
NetC175_2: C175.2 R82.1 R87.2 U9.8(FB2)
NetC178_1: C178.1 U9.2(SS1)
NetC179_1: C179.1 U9.7(SS2)
NetC186_1: C186.1 R79.1 R90.2 U10.10(BIAS)
NetC187_1: C187.1 U10.15(SS)
NetC192_2: C192.2 R93.1 R96.2 U11.5(ADJ)
NetC193_1: C193.1(+) L17.1 LF7.3
NetC194_1: C194.1 EXT5V_FMC12V.1 L17.2
NetL6_1: L6.1 LMX_LDO.2 R73.2
NetL9_1: L9.1 L10.1 L13.1 LMK_LDO.2 R40.2
NetLF7_2: LF7.2 S1.1
NetR39_2: R39.2 U5.8(~{SD})
NetR70_2: R70.2 U7.1(EN)
NetR71_2: R71.2 U8.8(~{SD})
NetR80_2: R80.2 R89.2 U10.11(EN)
NetR85_1: R85.1 R88.2 U10.16(FB)

Not connected (* = marked no-connect by the designer): 5VDC 3*; U5 2(NC)* 7(NC)*; U8 2(NC)* 7(NC)*; U10 2(NC)* 3(NC)* 4(NC)* 9(PG)* 13(NC)* 14(NC)* 17(NC)*

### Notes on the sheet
- 3.3V supply to clocks (LMK, LMX) and LEDs
- 1.9V and 1.2V supply to LM15851 / ADC12X3500RF
- 12V main supply, from jack or via FMC connector to regulators
- (near SH-5V_12V_1_2) Add text label: "5V VIA JACK" and "12V VIA FMC, Install R90 for 12V operation"
- (near 5VDC) Locate at edge opposite FMC connector

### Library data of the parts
1V2ADC_INT 1V2ADC_LDO 1V9ADC 1V9INT LMK_INT LMK_LDO LMX_INT LMX_LDO = TSW-102-07-G-S: Header, TH, 100mil, 2x1, Gold plated, 230 mil above insulator; Manufacturer: Samtec, Inc.; U/M: EA
5VDC = PJ-202AH: Connector, DC Jack 2.1X5.5 mm, TH; Manufacturer: CUI Inc.; SymbolCreator: a0799628; U/M: EA
12V = LTST-C190GKT: as Status1 on sheet SV600847E3_4_LMK04828
C116 C126 C144 C147 C148 C151 C153 C159 C164 C167 C176 C177 C185 C189 C191 C198 C199 = 06033C104JAT2A: CAP, CERM, 0.1uF, 25V, +/-5%, X7R, 0603; Manufacturer: AVX; Polarized: N; CompType: Capacitor; U/M: EA; Cap_F: 0.0000001; Tolerance_%: 5; ESR_Ohm: 0.05; Value1: 0.05 ohm; VDC_V: 25; TaMin_C: -55; TaMax_C: 125; Cap_Case: 0603
C117 C149 = 06035A331JAT2A: CAP, CERM, 330pF, 50V, +/-5%, C0G/NP0, 0603; Manufacturer: AVX; Polarized: N; CompType: Capacitor; U/M: EA; Cap_F: 0.00000000033; Tolerance_%: 5; ESR_Ohm: 0.071; Value1: 0.071 ohm; VDC_V: 50; TaMin_C: -55; TaMax_C: 125; Cap_Case: 0603
C127 C160 = C0603C475K8PACTU: CAP, CERM, 4.7uF, 10V, +/-10%, X5R, 0603; Manufacturer: Kemet; Polarized: N; CompType: Capacitor; U/M: EA; Cap_F: 0.0000047; Tolerance_%: 10; ESR_Ohm: 0.006; Value1: 0.006 ohm; IRMS_A: 7.24; TaMin_C: -55; TaMax_C: 85; Cap_Case: 0603
C128 C161 = 06031C103MAT2A: CAP, CERM, 0.01uF, 100V, +/-20%, X7R, 0603; Manufacturer: AVX; Polarized: N; CompType: Capacitor; U/M: EA; Cap_F: 0.00000001; Tolerance_%: 20; ESR_Ohm: 0.098; Value1: 0.098 ohm; VDC_V: 100; TaMin_C: -55; TaMax_C: 125; Cap_Case: 0603
C145 C146 C173 C184 = EMK212BJ106KG-T: CAP, CERM, 10uF, 16V, +/-10%, X5R, 0805; Manufacturer: Taiyo Yuden; Polarized: N; CompType: Capacitor; U/M: EA; Cap_F: 0.00001; Tolerance_%: 10; Value1: Unknown; VDC_V: 16; TaMin_C: -55; TaMax_C: 85; Cap_Case: 0805
C150 C152 C158 C163 C165 C166 C171 C172 C186 C188 C190 C195-C197 C202-C204 = C1608X5R1A106M: CAP, CERM, 10uF, 10V, +/-10%, C0G/NP0, 0603; Manufacturer: TDK; Polarized: N; CompType: Capacitor; U/M: EA; Cap_F: 0.00001; Tolerance_%: 10; ESR_Ohm: 0.0078; Value1: 0.0078 ohm; IRMS_A: 1.85; TaMin_C: -55; TaMax_C: 85; Cap_Case: 0603
C154 = 06035A100JAT2A: CAP, CERM, 10pF, 50V, +/-5%, C0G/NP0, 0603; Manufacturer: AVX; Polarized: N; CompType: Capacitor; U/M: EA; Cap_F: 0.00000000001; Tolerance_%: 5; ESR_Ohm: 0.403; Value1: 0.403 ohm; VDC_V: 50; TaMin_C: -55; TaMax_C: 125; Cap_Case: 0603
C155 = C1608X5R1C105K: as C108 on sheet SV600847E3_4_LMK04828
C156 C157 = GRM31CR60J476ME19L: CAP, CERM, 47uF, 6.3V, +/-20%, X5R, 1206; Manufacturer: MuRata; Polarized: N; CompType: Capacitor; U/M: EA; Cap_F: 0.000047; Tolerance_%: 20; ESR_Ohm: 0.003; Value1: 0.003 ohm; VDC_V: 6.3; TaMin_C: -55; TaMax_C: 85; Cap_Case: 1206
C162 = GRM188R71E332KA01D: CAP, CERM, 3300pF, 25V, +/-10%, X7R, 0603; Manufacturer: MuRata; Polarized: N; CompType: Capacitor; U/M: EA; Cap_F: 0.0000000033; Tolerance_%: 10; VDC_V: 25; TaMin_C: -55; TaMax_C: 125; Cap_Case: 0603
C168 = C1608X7R1C224K: CAP, CERM, 0.22uF, 16V, +/-10%, X7R, 0603; Manufacturer: TDK; Polarized: N; CompType: Capacitor; U/M: EA; Cap_F: 0.00000022; Tolerance_%: 10; ESR_Ohm: 0.0125; Value1: 0.0125 ohm; VDC_V: 16; TaMin_C: -55; TaMax_C: 125; Cap_Case: 0603
C169 C170 = GRM155R60J104KA01D: CAP, CERM, 0.1uF, 6.3V, +/-10%, X5R, 0402; Manufacturer: MuRata; Polarized: N; CompType: Capacitor; U/M: EA; Cap_F: 0.0000001; Tolerance_%: 10; VDC_V: 6.3; TaMin_C: -55; TaMax_C: 85; Cap_Case: 0402
C174 C175 = GRM188R71C273KA01D: CAP, CERM, 0.027uF, 16V, +/-10%, X7R, 0603; Manufacturer: MuRata; Polarized: N; CompType: Capacitor; U/M: EA; Cap_F: 0.000000027; Tolerance_%: 10; VDC_V: 16; TaMin_C: -55; TaMax_C: 125; Cap_Case: 0603
C178 C179 = 06033C393KAT2A: CAP, CERM, 0.039uF, 25V, +/-10%, X7R, 0603; Manufacturer: AVX; Polarized: N; CompType: Capacitor; U/M: EA; Cap_F: 0.000000039; Tolerance_%: 10; ESR_Ohm: 0.056; Value1: 0.056 ohm; VDC_V: 25; TaMin_C: -55; TaMax_C: 125; Cap_Case: 0603
C180-C183 = GRM31CR61A226ME19L: CAP, CERM, 22uF, 10V, +/-20%, X5R, 1206; Manufacturer: MuRata; Polarized: N; CompType: Capacitor; U/M: EA; Cap_F: 0.000022; Tolerance_%: 20; ESR_Ohm: 0.007; Value1: 0.007 ohm; VDC_V: 10; TaMin_C: -55; TaMax_C: 85; Cap_Case: 1206
C187 = 06035A561JAT2A: CAP, CERM, 560pF, 50V, +/-5%, C0G/NP0, 0603; Manufacturer: AVX; Polarized: N; CompType: Capacitor; U/M: EA; Cap_F: 0.00000000056; Tolerance_%: 5; ESR_Ohm: 0.059; Value1: 0.059 ohm; VDC_V: 50; TaMin_C: -55; TaMax_C: 125; Cap_Case: 0603
C192 = GRM188R71C472KA01D: CAP, CERM, 4700pF, 16V, +/-10%, X7R, 0603; Manufacturer: MuRata; Polarized: N; CompType: Capacitor; U/M: EA; Cap_F: 0.0000000047; Tolerance_%: 10; VDC_V: 16; TaMin_C: -55; TaMax_C: 125; Cap_Case: 0603
C193 = EEE-FC1E101P: CAP, AL, 100uF, 25V, +/-20%, 0.3 ohm, SMD; Manufacturer: Panasonic; Polarized: Y; CompType: Capacitor; U/M: EA; Cap_F: 0.0001; Tolerance_%: 20; Value1: 0.3 ohm; VDC_V: 25; ESR_Ohm: 0.3; IRMS_A: 0.45; TaMin_C: -40; TaMax_C: 105; Cap_Case: F
C194 = GRM32DC81E106KA12L: CAP, CERM, 10uF, 25V, +/-10%, X6S, 1210; Manufacturer: MuRata; Polarized: N; CompType: Capacitor; U/M: EA; Cap_F: 0.00001; Tolerance_%: 10; VDC_V: 25; TaMin_C: -55; TaMax_C: 105; Cap_Case: 1210
D11 D12 = MBRS540T3G: Diode, Schottky, 40V, 5A, SMC; Manufacturer: ON Semiconductor; U/M: EA; Vf_V: 0.5; Io_A: 5; Vr_V: 40; TJmax_C: 150; RJC_CperW: 12
EXT5V_FMC12V = PBC03SAAN: Header, TH, 100mil, 1x3, Gold plated, 230 mil above insulator; Manufacturer: Sullins Connector Solutions; U/M: EA
L6 L9 L10 L13 L15-L18 = BLM18SG260TN1D: 6A Ferrite Bead, 26 ohm @ 100MHz, SMD; Manufacturer: MuRata; Imax_A: 6; DCR_ohm: 0.007; Value1: 0.007 ohm; ZTyp@100MHz_Ohm: 26; U/M: EA
L7 L14 L20 = BLM18SG121TN1D: 3A Ferrite Bead, 120 ohm @ 100MHz, SMD; Manufacturer: MuRata; Imax_A: 3; DCR_ohm: 0.025; Value1: 0.025 ohm; ZTyp@100MHz_Ohm: 120; U/M: EA
L8 = CDRH6D28NP-3R0NC: Inductor, Shielded Drum Core, Ferrite, 3uH, 3A, 0.024 ohm, SMD; Manufacturer: Sumida; Ind_H: 3.0E-6; Imax_A: 3; Irms: 3A @ 30C rise; Isat: 3A @ 35% inductance drop; DCR_ohm: 0.024; U/M: EA
L11 = MSS1038-702NLB: Inductor, Shielded Drum Core, Ferrite, 7uH, 4.35A, 0.03 ohm, SMD; Manufacturer: Coilcraft; Ind_H: 7.0E-6; Imax_A: 4.35; Irms: 4.35A @ 40C rise; Isat: 5.6A @ 30% inductance drop; DCR_ohm: 0.03; U/M: EA
L12 = 744325550: Inductor, Shielded Drum Core, Superflux, 5.5uH, 10A, 0.0112 ohm, SMD; Manufacturer: Wurth Elektronik eiSos; Ind_H: 5.5E-6; Imax_A: 10; Irms: 10A @ 50C rise; Isat: 12A @ 30% inductance drop; DCR_ohm: 0.0112; U/M: EA
LF7 = ACM7060-301-2PL-TL: Coupled inductor, 5A, 0.01 ohm, SMD; Manufacturer: TDK; SymbolCreator: a0799628; Config: Common Chokes; Value: uH; DCR_Ohm: 0.01; Isat: 5; U/M: EA
R39 R71 R80 = RC0603JR-071KL: RES, 1.0k ohm, 5%, 0.1W, 0603; Manufacturer: Yageo America; CompType: Resistor; Res_ohm: 1000; Value_Code: 1k00; Tolerance_%: 5; Power_W: 0.1; VDC_V: 50; TempCo: 100 ppm/C; EIA_Code: E24; U/M: EA
R40 R42 R73 R75 R83 R84 R92 R95 = CSNL1206FT2L00: RES, 0.002 ohm, 1%, 1W, 1206; Manufacturer: Stackpole Electronics Inc; CompType: Resistor; Value_Code: R002; Tolerance_%: 1; TempCo: 50 ppm/C; U/M: EA
R41 R74 = CRCW060310K7FKEA: RES, 10.7k ohm, 1%, 0.1W, 0603; Manufacturer: Vishay-Dale; CompType: Resistor; Res_ohm: 10700; Value_Code: 10k7; Tolerance_%: 1; Power_W: 0.1; VDC_V: 75; TempCo: 100 ppm/C; EIA_Code: E96; U/M: EA
R49 R77 = RC0603FR-074K64L: RES, 4.64k ohm, 1%, 0.1W, 0603; Manufacturer: Yageo America; CompType: Resistor; Res_ohm: 4640; Value_Code: 4k64; Tolerance_%: 1; Power_W: 0.1; VDC_V: 150; TempCo: 200 ppm/C; EIA_Code: E96; U/M: EA
R70 = RC0603JR-0710KL: RES, 10k ohm, 5%, 0.1W, 0603; Manufacturer: Yageo America; CompType: Resistor; Res_ohm: 10000; Value_Code: 10k0; Tolerance_%: 5; Power_W: 0.1; VDC_V: 50; TempCo: 100 ppm/C; EIA_Code: E24; U/M: EA
R72 = CRCW060382K5FKEA: RES, 82.5k ohm, 1%, 0.1W, 0603; Manufacturer: Vishay-Dale; CompType: Resistor; Res_ohm: 82500; Value_Code: 82k5; Tolerance_%: 1; Power_W: 0.1; VDC_V: 75; TempCo: 100 ppm/C; EIA_Code: E96; U/M: EA
R76 = CRCW060322K1FKEA: RES, 22.1k ohm, 1%, 0.1W, 0603; Manufacturer: Vishay-Dale; CompType: Resistor; Res_ohm: 22100; Value_Code: 22k1; Tolerance_%: 1; Power_W: 0.1; VDC_V: 75; TempCo: 100 ppm/C; EIA_Code: E96; U/M: EA
R78 = RC0603FR-0710RL: RES, 10.0 ohm, 1%, 0.1W, 0603; Manufacturer: Yageo America; CompType: Resistor; Res_ohm: 10; Value_Code: 10R0; Tolerance_%: 1; Power_W: 0.1; VDC_V: 150; TempCo: 200 ppm/C; EIA_Code: E96; U/M: EA
R79 = CRCW0603732RFKEA: RES, 732 ohm, 1%, 0.1W, 0603; Manufacturer: Vishay-Dale; CompType: Resistor; Value_Code: 732R; Tolerance_%: 1; Power_W: 0.1; VDC_V: 75; TempCo: 100 ppm/C; EIA_Code: E96; U/M: EA
R81 = CRCW060316K2FKEA: RES, 16.2k ohm, 1%, 0.1W, 0603; Manufacturer: Vishay-Dale; CompType: Resistor; Res_ohm: 16200; Value_Code: 16k2; Tolerance_%: 1; Power_W: 0.1; VDC_V: 75; TempCo: 100 ppm/C; EIA_Code: E96; U/M: EA
R82 = CRCW06037K87FKEA: RES, 7.87k ohm, 1%, 0.1W, 0603; Manufacturer: Vishay-Dale; CompType: Resistor; Res_ohm: 7870; Value_Code: 7k87; Tolerance_%: 1; Power_W: 0.1; VDC_V: 75; TempCo: 100 ppm/C; EIA_Code: E96; U/M: EA
R85 = CRCW06032K49FKEA: RES, 2.49k ohm, 1%, 0.1W, 0603; Manufacturer: Vishay-Dale; CompType: Resistor; Res_ohm: 2490; Value_Code: 2k49; Tolerance_%: 1; Power_W: 0.1; VDC_V: 75; TempCo: 100 ppm/C; EIA_Code: E96; U/M: EA
R86 R87 = CRCW06035K90FKEA: RES, 5.90k ohm, 1%, 0.1W, 0603; Manufacturer: Vishay-Dale; CompType: Resistor; Res_ohm: 5900; Value_Code: 5k90; Tolerance_%: 1; Power_W: 0.1; VDC_V: 75; TempCo: 100 ppm/C; EIA_Code: E96; U/M: EA
R88 = CRCW06034K99FKEA: RES, 4.99k ohm, 1%, 0.1W, 0603; Manufacturer: Vishay-Dale; CompType: Resistor; Res_ohm: 4990; Value_Code: 4k99; Tolerance_%: 1; Power_W: 0.1; VDC_V: 75; TempCo: 100 ppm/C; EIA_Code: E96; U/M: EA
R89 = CRCW06032K80FKEA: RES, 2.80k ohm, 1%, 0.1W, 0603; Manufacturer: Vishay-Dale; CompType: Resistor; Res_ohm: 2800; Value_Code: 2k80; Tolerance_%: 1; Power_W: 0.1; VDC_V: 75; TempCo: 100 ppm/C; EIA_Code: E96; U/M: EA
R90 = RC0603FR-07402RL: RES, 402 ohm, 1%, 0.1W, 0603; Manufacturer: Yageo America; CompType: Resistor; Value_Code: 402R; Tolerance_%: 1; Power_W: 0.1; VDC_V: 150; TempCo: 200 ppm/C; EIA_Code: E96; U/M: EA
R93 = RC0603FR-071KL: RES, 1.00k ohm, 1%, 0.1W, 0603; Manufacturer: Yageo America; CompType: Resistor; Res_ohm: 1000; Value_Code: 1k00; Tolerance_%: 1; Power_W: 0.1; VDC_V: 150; TempCo: 200 ppm/C; EIA_Code: E96; U/M: EA
R94 = CRCW12061K00JNEA: RES, 1.0k ohm, 5%, 0.25W, 1206; Manufacturer: Vishay-Dale; CompType: Resistor; Res_ohm: 1000; Value_Code: 1k00; Tolerance_%: 5; Power_W: 0.25; VDC_V: 200; TempCo: 200 ppm/C; EIA_Code: E24; U/M: EA
R96 = RC0603FR-07357RL: RES, 357 ohm, 1%, 0.1W, 0603; Manufacturer: Yageo America; CompType: Resistor; Value_Code: 357R; Tolerance_%: 1; Power_W: 0.1; VDC_V: 150; TempCo: 200 ppm/C; EIA_Code: E96; U/M: EA
S1 = L101011MS02Q: SWITCH SLIDE SPST 4A PCB, TH; Manufacturer: C&K Components; Symbol Creator: a0411947; VDC_V: 125; SwitchFunction: Off-On; PositionCount: 1; CurrentRating_mA: 4000
SH-1V2ADC_INT_1_2 SH-1V2ADC_LDO_1_2 SH-1V9ADC_1_2 SH-1V9INT_1_2 SH-5V_12V_1_2 SH-LMK_INT_1_2 SH-LMK_LDO_1_2 SH-LMX_INT_1_2 SH-LMX_LDO_1_2 = SNT-100-BK-G: Shunt, 100mil, Gold plated, Black; Manufacturer: Samtec, Inc.; Alternate Manufacturer: 3M; Alternate PartNumber: 969102-0000-DA; Value: 1x2; Note: You can "mate" this to a header by matching the designator.  i.e. use SH-J3 for header J3
U5 U8 = LP3878MR-ADJ/NOPB: Micropower 800mA Low Noise "Ceramic Stable" Adjustable Voltage Regulator for 1V to 5V Applications, 8-pin PSOP, Pb-Free; Manufacturer: National Semiconductor; PackageTopMarking: NSXYTT*3878*MRADJ; PowerWise: N; CompType: LDO IC
U7 = TPS54327DDA: 3-A OUTPUT SINGLE SYNCRONOUS STEP DOWN SWITCHER WITH INTEGRATED FET(SWIFT), DDA0008B; Alternate Manufacturer: None; Manufacturer: Texas Instruments; SymbolCreator: a0411947; CompType: IC; U/M: EA
U9 = LM26400YSDE/NOPB: Dual 2A, 500kHz Wide Input Range Buck Regulator, 16-pin LLP, Pb-Free; Manufacturer: National Semiconductor; PackageTopMarking: NS*UZXYTT*L26400Y; PowerWise: N; CompType: Switcher
U10 = TPS74901RGW: 3.0A Low Dropout Linear Regulator with Programmable Soft-Start, RGW0020A; Alternate Manufacturer: None; Manufacturer: Texas Instruments; SymbolCreator: a0411947; CompType: IC; U/M: EA
U11 = LP38513TJ-ADJ/NOPB: 3A Fast-Transient Response Adjustable Low-Dropout Linear Voltage Regulator, 5-pin TO-263 Thin, Pb-Free; Manufacturer: National Semiconductor; PackageTopMarking: NSUZXYTTE#*LP38513*TJ-ADJ; PowerWise: N; CompType: LDO IC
